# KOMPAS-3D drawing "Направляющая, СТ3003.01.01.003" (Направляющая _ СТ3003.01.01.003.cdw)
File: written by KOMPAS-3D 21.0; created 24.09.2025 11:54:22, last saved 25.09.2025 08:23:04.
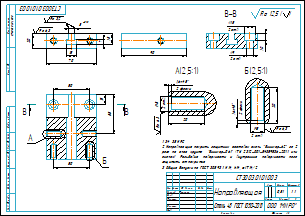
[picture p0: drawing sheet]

Sheet 1: A3, landscape

Document properties: Знак неуказанной шероховатости: 4; Параметр неуказанной шероховатости: Ra 12,5; Масса: 0.806848; Полное имя файла: ..\..\3D\Кронштейн _ СТ3003.01.01.000\Направляющая _ СТ3003.01.01.003.m3d

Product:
- Part/product: Направляющая  | designation СТ3003.01.01.003
    Материал: Сталь 45  ГОСТ 1050-2013 (density 7810 kg/m3)
    Масса: 0.806848

Title block, sheet 1: Наименование: Направляющая; designation: СТ3003.01.01.003; Материал: Сталь 45  ГОСТ 1050-2013; Масса: 0,81; Количество листов документа: 1; organisation: ООО "МИРО"; Форматы листов документа: A3; stored path: C:\Users\1\Yandex.Disk\Документы\Новая папка\Стапель №2\Стапель _ СТ3003.00.00.000\Опора _ СТ3003.01.00.000\2D\Кронштейн _ СТ3003.01.01.000\Направляющая _ СТ3003.01.01.003.cdw; Разработал: Тимонин

Views: Вид 1, Справа, Проекционный вид 2, Местный разрез 1, Проекционный вид 3, Выносной элемент 4, Выносной элемент 5, Разрез В-В, Выносной элемент А, Выносной элемент, Выносной элемент Б
Referenced files in C:\Users\1\Yandex.Disk\Документы\Новая папка\Стапель №2\Стапель _ СТ3003.00.00.000\Опора _ СТ3003.01.00.000\3D\Кронштейн _ СТ3003.01.01.000\: Направляющая _ СТ3003.01.01.003.m3d
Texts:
  Ra 3,2
  Ra 6,3
  Ra 12,5
  Ra 12,5 ( )
  СТ3003.01.01.000
  СТ3003.01.01.003 Направляющая
Dimensions and other numbers on the sheet: 8; 15; 7; 70; 20; 50; 55; 6; 90; 2 отв.; 1,6; 2 фаски; 9; 10; 1:1; 1; 0,81

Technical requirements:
  34...38 HRC.
  Направляющию покрыть защитным составом эмаль "Виникор-62" за 2
  раза по слою грунта  "Виникор-061" (ТУ 2312-001-54359536-2011 или
  аналог). Резьбовые поверхности и внутренние поверхности паза
  защитить от покрытия.
  Общие допуски по ГОСТ 30893.1: Н14, h14, ± IT14/2.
